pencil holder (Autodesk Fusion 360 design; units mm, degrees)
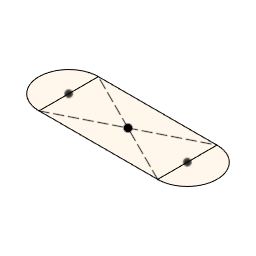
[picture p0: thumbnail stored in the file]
sketch "Sketch1" plane through (0, 0, 0) normal (0, 1, 0) x axis (1, 0, 0)
  line L1 (76.2, -38.1) -> (-76.2, -38.1)
  line L2 (76.2, 38.1) -> (76.2, -38.1)
  line L3 (-76.2, 38.1) -> (76.2, 38.1)
  line L4 (-76.2, -38.1) -> (-76.2, 38.1)
  line L5 (76.2, 38.1) -> (-76.2, -38.1)
  line L6 (-76.2, 38.1) -> (76.2, -38.1)
  arc A1 centre (-76.2, 0) radius 38.1 clockwise from (-76.2, -38.1) to (-76.2, 38.1)
  arc A2 centre (76.2, 0) radius 38.1 clockwise from (76.2, 38.1) to (76.2, -38.1)
  point P6 (0, 0)
  point P1 (0, 0)
  point P4 (76.2, 38.1)
  point P5 (-76.2, 38.1)
  point P3 (76.2, -38.1)
  perpendicular L1 L2
  parallel L1 L3
  parallel L2 L4
  horizontal L1
  coincident L5 P6
  coincident L6 P6
  coincident P1 P6
  tangent L1 A1
  tangent L3 A2
  dimension "d1" distance P4 P5 = 152.4
  dimension "d2" distance P3 P4 = 76.2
